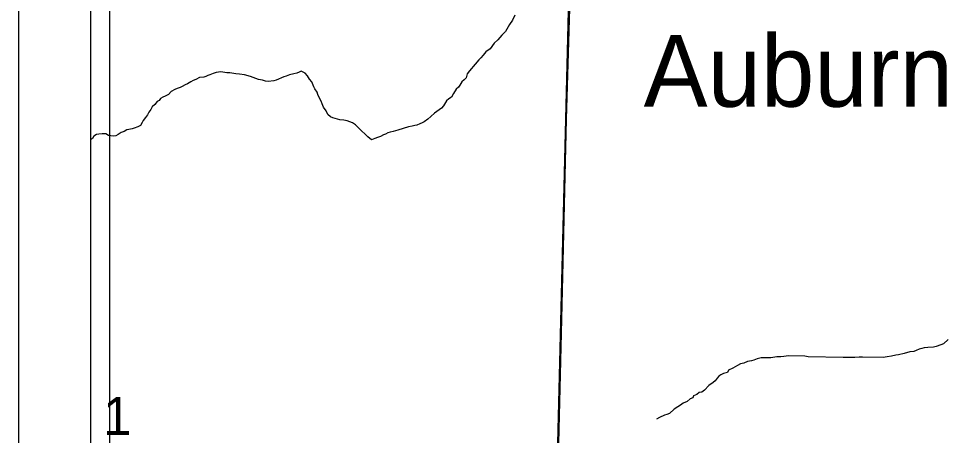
# Model space of a CAD drawing. Extents: x 0 to 34, y -2.3 to 22.
# Drawn here: x 2 to 3.022, y 19.952 to 20.411 of the extents above; entities that cross this region are included whole.
import ezdxf

# ---------------------------------------------------------------- set-up
doc = ezdxf.new("R2010")
doc.units = 0
for name, color, linetype in [('GM_X_County', 7, 'Continuous'), ('GM_X_Minor_River', 7, 'Continuous'), ('GM_X_Section', 7, 'Continuous'), ('GM_X_Section_Text', 7, 'Continuous'), ('GM_X_Township', 7, 'Continuous'), ('GM_X_Township_Road', 7, 'Continuous'), ('GM_X_Unincorporated_Text', 7, 'Continuous'), ('SH_Data', 7, 'Continuous')]:
    doc.layers.add(name, color=color, linetype=linetype)

msp = doc.modelspace()

# ---------------------------------------------------------------- linework, layer by layer
at = {"layer": 'GM_X_County'}
msp.add_line((2.0792, 20.8994), (2.0792, 14.4971), dxfattribs=at)
at = {"layer": 'GM_X_Minor_River'}
for p, q in [((2.5438, 20.4088), (2.5402, 20.404)), ((2.5462, 20.4145), (2.5438, 20.4088)), ((2.5374, 20.3991), (2.5359, 20.3965)), ((2.5402, 20.404), (2.5374, 20.3991)), ((2.5277, 20.3872), (2.5234, 20.3835)), ((2.532, 20.3924), (2.5277, 20.3872)), ((2.5359, 20.3965), (2.532, 20.3924)), ((2.5191, 20.3772), (2.5144, 20.3739)), ((2.5234, 20.3835), (2.5191, 20.3772)), ((2.5089, 20.3675), (2.5066, 20.3653)), ((2.5113, 20.3705), (2.5089, 20.3675)), ((2.5144, 20.3739), (2.5113, 20.3705)), ((2.5027, 20.3605), (2.4964, 20.353)), ((2.5066, 20.3653), (2.5027, 20.3605)), ((2.2038, 20.3462), (2.1992, 20.3456)), ((2.2061, 20.347), (2.2038, 20.3462)), ((2.2084, 20.348), (2.2061, 20.347)), ((2.2107, 20.3487), (2.2084, 20.348)), ((2.2142, 20.3502), (2.2107, 20.3487)), ((2.2176, 20.3512), (2.2142, 20.3502)), ((2.2199, 20.3515), (2.2176, 20.3512)), ((2.2226, 20.3519), (2.2199, 20.3515)), ((2.2294, 20.3509), (2.2226, 20.3519)), ((2.2325, 20.3509), (2.2294, 20.3509)), ((2.2393, 20.3499), (2.2325, 20.3509)), ((2.2431, 20.3495), (2.2393, 20.3499)), ((2.2488, 20.3486), (2.2431, 20.3495)), ((2.2552, 20.3469), (2.2488, 20.3486)), ((2.2642, 20.3436), (2.2552, 20.3469)), ((2.2921, 20.3467), (2.2836, 20.3427)), ((2.2944, 20.3474), (2.2921, 20.3467)), ((2.2982, 20.3488), (2.2944, 20.3474)), ((2.3028, 20.3499), (2.2982, 20.3488)), ((2.3062, 20.3505), (2.3028, 20.3499)), ((2.3089, 20.3516), (2.3062, 20.3505)), ((2.3112, 20.3527), (2.3089, 20.3516)), ((2.3154, 20.3507), (2.3112, 20.3527)), ((2.3179, 20.3476), (2.3154, 20.3507)), ((2.3202, 20.3441), (2.3179, 20.3476)), ((2.4937, 20.3497), (2.4928, 20.3455)), ((2.4964, 20.353), (2.4937, 20.3497)), ((2.18, 20.3358), (2.1777, 20.3347)), ((2.1835, 20.3376), (2.18, 20.3358)), ((2.1858, 20.3387), (2.1835, 20.3376)), ((2.1896, 20.3409), (2.1858, 20.3387)), ((2.1923, 20.3424), (2.1896, 20.3409)), ((2.195, 20.3434), (2.1923, 20.3424)), ((2.1992, 20.3456), (2.195, 20.3434)), ((2.2684, 20.3427), (2.2642, 20.3436)), ((2.2718, 20.3419), (2.2684, 20.3427)), ((2.2748, 20.3414), (2.2718, 20.3419)), ((2.2809, 20.3421), (2.2748, 20.3414)), ((2.2836, 20.3427), (2.2809, 20.3421)), ((2.3227, 20.341), (2.3202, 20.3441)), ((2.3249, 20.3356), (2.3227, 20.341)), ((2.326, 20.3333), (2.3249, 20.3356)), ((2.4858, 20.3373), (2.4842, 20.3351)), ((2.4878, 20.3411), (2.4858, 20.3373)), ((2.4905, 20.3433), (2.4878, 20.3411)), ((2.4928, 20.3455), (2.4905, 20.3433)), ((2.1615, 20.3253), (2.1588, 20.3242)), ((2.165, 20.3271), (2.1615, 20.3253)), ((2.1681, 20.3304), (2.165, 20.3271)), ((2.1719, 20.3326), (2.1681, 20.3304)), ((2.1746, 20.3337), (2.1719, 20.3326)), ((2.1777, 20.3347), (2.1746, 20.3337)), ((2.3286, 20.3295), (2.326, 20.3333)), ((2.3293, 20.3272), (2.3286, 20.3295)), ((2.3311, 20.323), (2.3293, 20.3272)), ((2.4787, 20.328), (2.4764, 20.3243)), ((2.4815, 20.3329), (2.4787, 20.328)), ((2.4842, 20.3351), (2.4815, 20.3329)), ((2.1499, 20.3161), (2.1472, 20.3135)), ((2.1526, 20.3194), (2.1499, 20.3161)), ((2.1549, 20.3205), (2.1526, 20.3194)), ((2.1561, 20.3227), (2.1549, 20.3205)), ((2.1588, 20.3242), (2.1561, 20.3227)), ((2.3329, 20.3199), (2.3311, 20.323)), ((2.3343, 20.3168), (2.3329, 20.3199)), ((2.3358, 20.313), (2.3343, 20.3168)), ((2.471, 20.3202), (2.4678, 20.3146)), ((2.4737, 20.3224), (2.471, 20.3202)), ((2.4764, 20.3243), (2.4737, 20.3224)), ((2.1432, 20.3075), (2.142, 20.3045)), ((2.1456, 20.3105), (2.1432, 20.3075)), ((2.1472, 20.3135), (2.1456, 20.3105)), ((2.3387, 20.3091), (2.3358, 20.313)), ((2.3405, 20.3052), (2.3387, 20.3091)), ((2.3435, 20.3025), (2.3405, 20.3052)), ((2.4577, 20.3065), (2.4538, 20.3028)), ((2.4631, 20.3102), (2.4577, 20.3065)), ((2.4654, 20.312), (2.4631, 20.3102)), ((2.4678, 20.3146), (2.4654, 20.312)), ((2.1361, 20.2963), (2.1341, 20.2929)), ((2.1373, 20.2985), (2.1361, 20.2963)), ((2.1397, 20.3019), (2.1373, 20.2985)), ((2.142, 20.3045), (2.1397, 20.3019)), ((2.3458, 20.3013), (2.3435, 20.3025)), ((2.3484, 20.3005), (2.3458, 20.3013)), ((2.3537, 20.2992), (2.3484, 20.3005)), ((2.3579, 20.2987), (2.3537, 20.2992)), ((2.3617, 20.2979), (2.3579, 20.2987)), ((2.3677, 20.2958), (2.3617, 20.2979)), ((2.3707, 20.2935), (2.3677, 20.2958)), ((2.4415, 20.2948), (2.4384, 20.2933)), ((2.4441, 20.2958), (2.4415, 20.2948)), ((2.4465, 20.2969), (2.4441, 20.2958)), ((2.4503, 20.2999), (2.4465, 20.2969)), ((2.4538, 20.3028), (2.4503, 20.2999)), ((2.113, 20.2854), (2.1096, 20.2829)), ((2.1161, 20.2865), (2.113, 20.2854)), ((2.1192, 20.288), (2.1161, 20.2865)), ((2.1215, 20.2887), (2.1192, 20.288)), ((2.1249, 20.2893), (2.1215, 20.2887)), ((2.1272, 20.29), (2.1249, 20.2893)), ((2.1311, 20.2915), (2.1272, 20.29)), ((2.1341, 20.2929), (2.1311, 20.2915)), ((2.3752, 20.2892), (2.3707, 20.2935)), ((2.3774, 20.2869), (2.3752, 20.2892)), ((2.3815, 20.2833), (2.3774, 20.2869)), ((2.4066, 20.285), (2.4039, 20.2835)), ((2.4089, 20.2857), (2.4066, 20.285)), ((2.4124, 20.2864), (2.4089, 20.2857)), ((2.4173, 20.2878), (2.4124, 20.2864)), ((2.4235, 20.2895), (2.4173, 20.2878)), ((2.4292, 20.2913), (2.4235, 20.2895)), ((2.4334, 20.2923), (2.4292, 20.2913)), ((2.4361, 20.293), (2.4334, 20.2923)), ((2.4384, 20.2933), (2.4361, 20.293)), ((2.0813, 20.2786), (2.0792, 20.2773)), ((2.0829, 20.2813), (2.0813, 20.2786)), ((2.0856, 20.2831), (2.0829, 20.2813)), ((2.0883, 20.2834), (2.0856, 20.2831)), ((2.0921, 20.2837), (2.0883, 20.2834)), ((2.0959, 20.2836), (2.0921, 20.2837)), ((2.0989, 20.282), (2.0959, 20.2836)), ((2.1015, 20.2816), (2.0989, 20.282)), ((2.1046, 20.2811), (2.1015, 20.2816)), ((2.1069, 20.2814), (2.1046, 20.2811)), ((2.1096, 20.2829), (2.1069, 20.2814)), ((2.3845, 20.2806), (2.3815, 20.2833)), ((2.3886, 20.2771), (2.3845, 20.2806)), ((2.392, 20.2785), (2.3886, 20.2771)), ((2.3951, 20.2796), (2.392, 20.2785)), ((2.3985, 20.281), (2.3951, 20.2796)), ((2.4016, 20.2825), (2.3985, 20.281)), ((2.4039, 20.2835), (2.4016, 20.2825)), ((3.01, 20.0497), (3.007, 20.049)), ((3.015, 20.0515), (3.01, 20.0497)), ((3.0181, 20.0525), (3.015, 20.0515)), ((3.0232, 20.0574), (3.0181, 20.0525)), ((2.8474, 20.0393), (2.8424, 20.0387)), ((2.8653, 20.0388), (2.8474, 20.0393)), ((2.9607, 20.0391), (2.9561, 20.0381)), ((2.9657, 20.0402), (2.9607, 20.0391)), ((2.9684, 20.0405), (2.9657, 20.0402)), ((2.9749, 20.0418), (2.9684, 20.0405)), ((2.981, 20.0436), (2.9749, 20.0418)), ((2.9856, 20.0442), (2.981, 20.0436)), ((2.9879, 20.0453), (2.9856, 20.0442)), ((2.9913, 20.0467), (2.9879, 20.0453)), ((2.9944, 20.0474), (2.9913, 20.0467)), ((2.9967, 20.0481), (2.9944, 20.0474)), ((3.0009, 20.0484), (2.9967, 20.0481)), ((3.007, 20.049), (3.0009, 20.0484)), ((2.7947, 20.0307), (2.7912, 20.0285)), ((2.7982, 20.0314), (2.7947, 20.0307)), ((2.8024, 20.0332), (2.7982, 20.0314)), ((2.8066, 20.0338), (2.8024, 20.0332)), ((2.8093, 20.0345), (2.8066, 20.0338)), ((2.8131, 20.036), (2.8093, 20.0345)), ((2.8173, 20.037), (2.8131, 20.036)), ((2.82, 20.0373), (2.8173, 20.037)), ((2.828, 20.0371), (2.82, 20.0373)), ((2.8348, 20.0381), (2.828, 20.0371)), ((2.839, 20.0384), (2.8348, 20.0381)), ((2.8424, 20.0387), (2.839, 20.0384)), ((2.8691, 20.0384), (2.8653, 20.0388)), ((2.9078, 20.0374), (2.8691, 20.0384)), ((2.9139, 20.0376), (2.9078, 20.0374)), ((2.9204, 20.0375), (2.9139, 20.0376)), ((2.9253, 20.0377), (2.9204, 20.0375)), ((2.9291, 20.038), (2.9253, 20.0377)), ((2.9516, 20.0375), (2.9291, 20.038)), ((2.9561, 20.0381), (2.9516, 20.0375)), ((2.7758, 20.0198), (2.7731, 20.0183)), ((2.7804, 20.0208), (2.7758, 20.0198)), ((2.7816, 20.0234), (2.7804, 20.0208)), ((2.7862, 20.0256), (2.7816, 20.0234)), ((2.7912, 20.0285), (2.7862, 20.0256)), ((2.7646, 20.0098), (2.7599, 20.0065)), ((2.7669, 20.0117), (2.7646, 20.0098)), ((2.7689, 20.0146), (2.7669, 20.0117)), ((2.7708, 20.0169), (2.7689, 20.0146)), ((2.7731, 20.0183), (2.7708, 20.0169)), ((2.7491, 19.9988), (2.7464, 19.9966)), ((2.7522, 19.9995), (2.7491, 19.9988)), ((2.7549, 20.0017), (2.7522, 19.9995)), ((2.7599, 20.0065), (2.7549, 20.0017)), ((2.7359, 19.9892), (2.7317, 19.9871)), ((2.7394, 19.9918), (2.7359, 19.9892)), ((2.7421, 19.9929), (2.7394, 19.9918)), ((2.7429, 19.9952), (2.7421, 19.9929)), ((2.7464, 19.9966), (2.7429, 19.9952)), ((2.7217, 19.9805), (2.7166, 19.976)), ((2.7255, 19.983), (2.7217, 19.9805)), ((2.7286, 19.9849), (2.7255, 19.983)), ((2.7317, 19.9871), (2.7286, 19.9849)), ((2.7055, 19.9714), (2.702, 19.9696)), ((2.7109, 19.9739), (2.7055, 19.9714)), ((2.7136, 19.9746), (2.7109, 19.9739)), ((2.7166, 19.976), (2.7136, 19.9746))]:
    msp.add_line(p, q, dxfattribs=at)
at = {"layer": 'GM_X_Section'}
for p, q in [((2.0792, 20.467), (2.0792, 19.5047)), ((2.5825, 19.4927), (2.6062, 20.454)), ((2.5825, 19.4927), (2.6062, 20.454))]:
    msp.add_line(p, q, dxfattribs=at)
at = {"layer": 'GM_X_Township'}
for p, q in [((2.0792, 20.467), (2.0792, 14.4971)), ((2.6032, 20.2998), (2.6078, 20.4547)), ((2.6032, 20.2998), (2.6078, 20.4547)), ((2.5976, 20.0643), (2.6032, 20.2998)), ((2.5976, 20.0643), (2.6032, 20.2998)), ((2.5838, 19.485), (2.5976, 20.0643)), ((2.5838, 19.485), (2.5976, 20.0643))]:
    msp.add_line(p, q, dxfattribs=at)
at = {"layer": 'GM_X_Township_Road'}
for p, q in [((2.6032, 20.2998), (2.6078, 20.4547)), ((2.5976, 20.0643), (2.6032, 20.2998)), ((2.5838, 19.485), (2.5976, 20.0643))]:
    msp.add_line(p, q, dxfattribs=at)
at = {"layer": 'SH_Data'}
for p, q in [((2, 21), (2, 14)), ((2.1, 20.9), (2.1, 14.1))]:
    msp.add_line(p, q, dxfattribs=at)

# ---------------------------------------------------------------- texts
at = {"layer": 'GM_X_Section_Text'}
msp.add_text('1', height=0.0419, rotation=0, dxfattribs=at).set_placement((2.093, 19.9521))
at = {"layer": 'GM_X_Unincorporated_Text'}
msp.add_text('Auburn', height=0.07898, rotation=0, dxfattribs=at).set_placement((2.688, 20.3136))

doc.saveas('drawing.dxf')
